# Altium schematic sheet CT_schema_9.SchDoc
size 287 x 160 mm
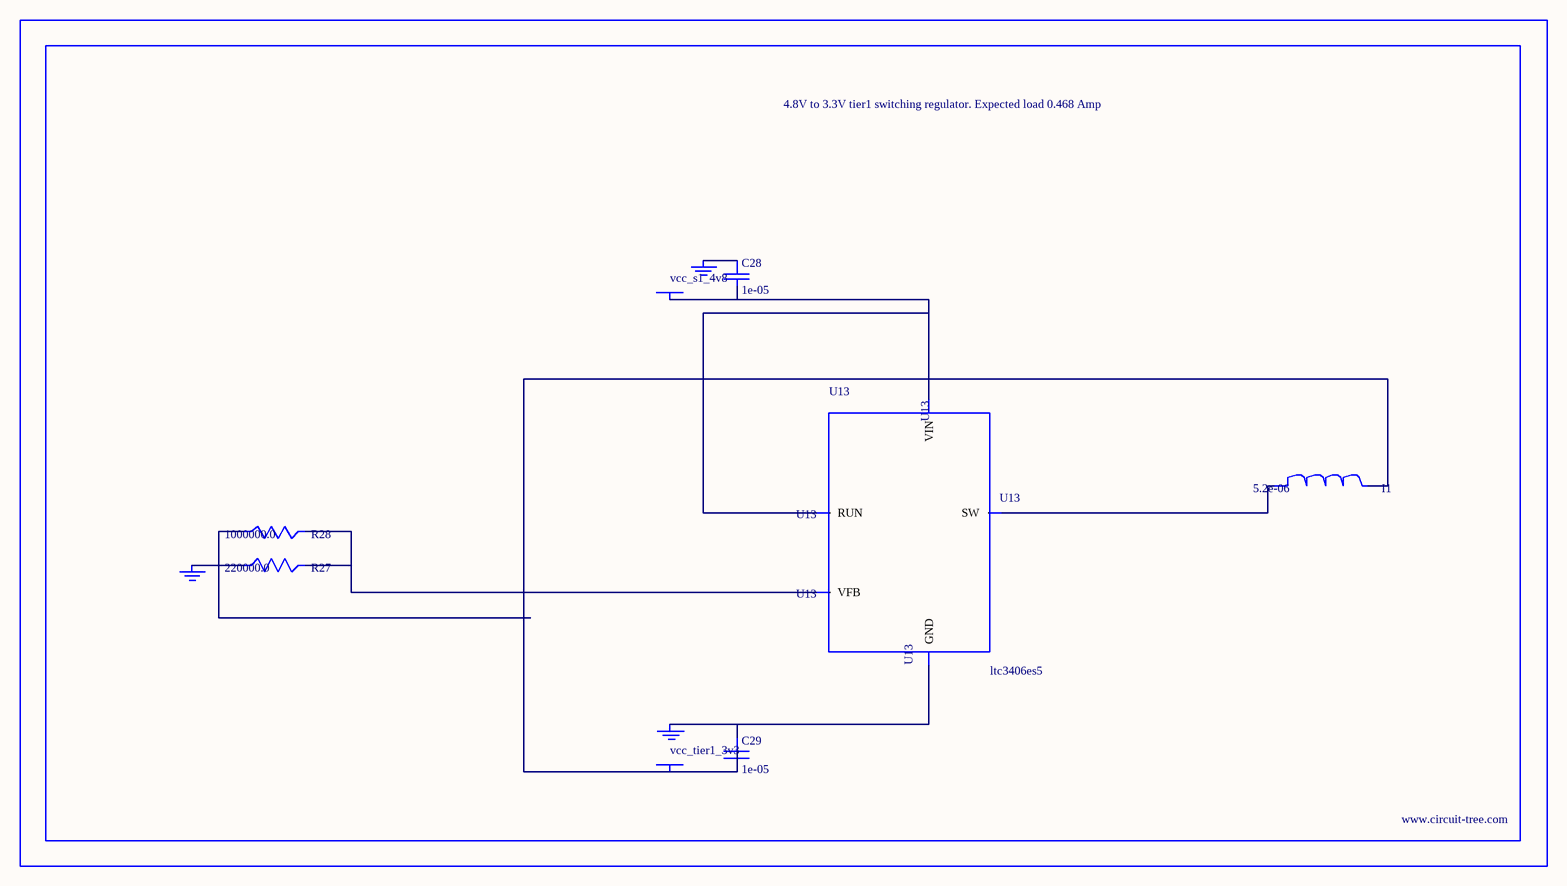
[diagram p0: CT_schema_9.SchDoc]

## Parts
BORDER8  (no value)
C28  1e-05  [C0805]
C29  1e-05  [C0805]
GND_INSTANCE_8_0  (no value)
GND_INSTANCE_8_1  (no value)
GND_INSTANCE_8_2  (no value)
I1  5.2e-06  [DR1040]
POWER_INSTANCE_8_0  vcc_tier1_3v3
POWER_INSTANCE_8_1  vcc_s1_4v8
R27  220000.0  [R0603]
R28  1000000.0  [R0603]
U13  ltc3406es5  [TSOT-23-5]

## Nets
NetC28_1: C28.1 GND_INSTANCE_8_1.0(GND)
NetC28_2: C28.2 POWER_INSTANCE_8_1.0(PWR) U13.1(RUN) U13.4(VIN)
NetC29_1: C29.1 GND_INSTANCE_8_0.0(GND) U13.2(GND)
NetC29_2: C29.2 I1.2 POWER_INSTANCE_8_0.0(PWR) R28.1
NetGND_INSTANCE_8_2_0: GND_INSTANCE_8_2.0(GND) R27.1
NetI1_1: I1.1 U13.3(SW)
NetR27_2: R27.2 R28.2 U13.5(VFB)

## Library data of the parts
BORDER8 = BORDER_PAGE8
C28 C29 = C0805C106K8RACTU
GND_INSTANCE_8_0-GND_INSTANCE_8_2 = GND
I1 = DR1040-5R2-R
POWER_INSTANCE_8_0 POWER_INSTANCE_8_1 = PWR
R27 = RC0603JR-07220KL
R28 = RC0603JR-071ML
